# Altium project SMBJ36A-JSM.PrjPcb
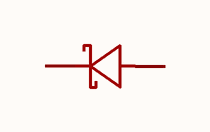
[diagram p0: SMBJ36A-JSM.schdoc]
1 sheet, 1 parts. Net scope: global (net labels, ports and power ports of the same name join across sheets).

## Sheet SMBJ36A-JSM.schdoc
size 127 x 101 mm

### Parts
D?  smbj36a-jsm  [SMB_L4.3-W3.6-LS5.3-RD]  (value not drawn)

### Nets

Not connected (* = marked no-connect by the designer): D? 1(K) 2(A)

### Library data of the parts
D? = smbj36a-jsm: 极性:单向;反向截止电压(Vrwm):36V;钳位电压:58.1V;峰值脉冲电流(Ipp):10.4A;峰值脉冲功率(Ppp):600W;击穿电压(VBR):44.2V;; Manufacturer: JSMSEMI(杰盛微); AddInBom: yes; ModelId: 314c1f1e2ff843d9bed33f9992fd5d20; ModelName: SMB_L4.32-W3.62-LS5.3-RD; ModelTransform: 208.661,142.5194,0,0,0,0,0,0,0; Polarity: 单向; Reverse Stand-Off Voltage (Vrwm): 36V; Clamping Voltage: 58.1V; Peak Pulse Current (Ipp): 10.4A; Peak Pulse Power Dissipation (Ppp): 600W; Voltage - Breakdown: 44.2V; Reverse Leakage Current (Ir): 1uA; Number of Channels: 单路; Type: TVS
